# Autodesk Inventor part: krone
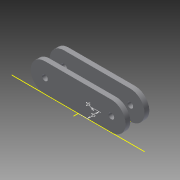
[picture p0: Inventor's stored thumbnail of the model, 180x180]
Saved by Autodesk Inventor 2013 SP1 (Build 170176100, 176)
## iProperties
Created: 2012-11
Part Number: krone
Material: Allgemein
Document SubType Name: Modeling
Designer: macuser
Density: 1 g/cm^3
Author: macuser
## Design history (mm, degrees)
sketch "Skizze1"
  geometry: L1 (140, 0)-(-140, 0) reference; L2 (0, -42)-(0, 42) reference; L3 (-70, 30)-(70, 30); L4 (70, 30)-(70, -30); L5 (70, -30)-(-70, -30); L6 (-70, -30)-(-70, 30); C1 r 30 at (-70, 0); 2 further points
  constraints: 8 end point, 2 midpoint, 2 parallel, 1 centre point, 1 horizontal, 1 perpendicular, 1 tangent, 1 vertical alignment, 4 other
  dimensions: "d0" = 140 distance of L4.end L5.end; "d1" = 60 distance of L3.end L4.end
extrude "Extrusion3" join sketch "Skizze1" distance "d43" = 50; taper "d44" = 0 deg
feature "Wandstärke2" dims "d45" = 10
sketch "Skizze4"
  geometry: C1 r 6 at (-70, 0); C2 r 6 at (70, 0); A1 r 30 centre (-70, 0) between (-70, 30) and (-70, -30) reference; A2 r 30 centre (70, 0) between (70, -30) and (70, 30) reference; 1 further point
  constraints: 2 centre point, 2 coincident
  dimensions: "d46" = 12 diameter of C1; "d47" = 12 diameter of C2
extrude "Extrusion4" cut sketch "Skizze4" distance "d48" = 50; taper "d49" = 0 deg
sketch "Skizze5"
  geometry: C1 r 6 at (0, 30) reference; C2 r 6 at (140, 30) reference; C3 r 35 at (0, 30); C4 r 35 at (140, 30); A1 r 30 centre (140, 30) between (140, 0) and (140, 60) reference; A2 r 30 centre (0, 30) between (0, 60) and (0, 0) reference; 1 further point
  constraints: 2 centre point, 2 coincident
  dimensions: "d50" = 70 diameter of C3; "d51" = 70 diameter of C4
extrude "Extrusion5" cut sketch "Skizze5" distance "d52" = 30; taper "d53" = 0 deg
sketch "Skizze6"
  geometry: L1 (70, -10)-(70, 60) reference; L2 (210, 0)-(-70, 0) reference; L3 (70, 0)-(70, 25); C1 r 6 at (70, 25)
  constraints: 2 end point, 1 centre point, 1 coincident, 1 midpoint
  dimensions: "d54" = 25 distance of L3.start L3.end; "d56" = 12 diameter of C1
extrude "Extrusion6" cut sketch "Skizze6" distance "d57" = 10; taper "d58" = 0 deg
node "Volumenkörper1"
